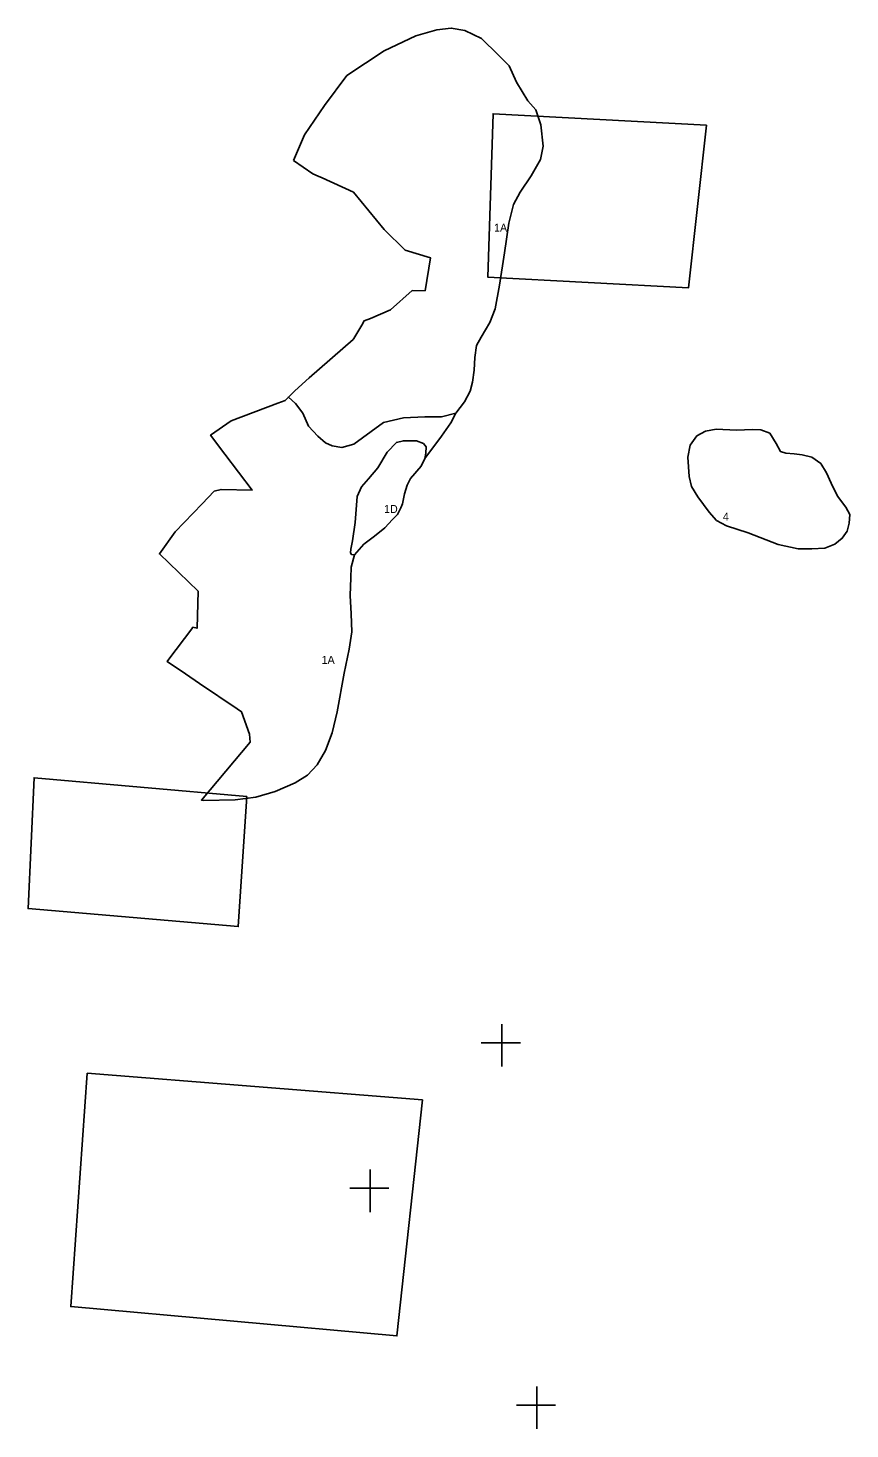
# Model space of a CAD drawing. Extents: x -439069 to -431150, y -1130245 to -1119273.
# Drawn here: x -439069 to -437837, y -1124070 to -1121968 of the extents above; entities that cross this region are included whole.
import ezdxf

# ---------------------------------------------------------------- set-up
doc = ezdxf.new("R2010")
doc.units = 0
for name, color, linetype in [('11510013_sesuvné území_Stav', 7, 'Continuous'), ('11540011_poddolované území_Stav', 7, 'Continuous'), ('svahové nestability přírodního charakteru dočasně uklidněné', 7, 'Continuous'), ('Svahové nestability přírodního charakteru uklidněné', 7, 'Continuous')]:
    doc.layers.add(name, color=color, linetype=linetype)

msp = doc.modelspace()

# ---------------------------------------------------------------- linework, layer by layer
at = {"layer": '11510013_sesuvné území_Stav'}
for p, q in [((-438358.9, -1123462.4), (-438358.9, -1123526.2)), ((-438389.6, -1123490.3), (-438331.1, -1123490.3)), ((-438556.1, -1123680.6), (-438556.1, -1123744.4)), ((-438586.7, -1123708.6), (-438528.2, -1123708.6)), ((-438306.5, -1124005.8), (-438306.5, -1124069.6)), ((-438337.1, -1124033.7), (-438278.6, -1124033.7))]:
    msp.add_line(p, q, dxfattribs=at)
at = {"layer": '11540011_poddolované území_Stav'}
for points in [[(-438052, -1122114), (-438372, -1122097), (-438380, -1122342), (-438079, -1122358), (-438052, -1122114)], [(-438741, -1123121), (-439060, -1123093), (-439069, -1123289), (-438754, -1123316), (-438741, -1123121)], [(-438477.5, -1123575.9), (-438980.2, -1123536.2), (-439005, -1123886), (-438516, -1123930), (-438477.5, -1123575.9)]]:
    msp.add_lwpolyline(points, dxfattribs=at)
at = {"layer": 'svahové nestability přírodního charakteru dočasně uklidněné'}
for points in [[(-438007, -1122571.7), (-438037.4, -1122570), (-438053.4, -1122572.9), (-438066.8, -1122580.1), (-438076.5, -1122594.1), (-438079.8, -1122612.2), (-438077.9, -1122641), (-438074.6, -1122656.3), (-438064.9, -1122671.7), (-438048.3, -1122694.5), (-438036.9, -1122707.1), (-438022, -1122715), (-437989.7, -1122725.5), (-437944.9, -1122743.3), (-437914.5, -1122749.4), (-437894.2, -1122749.5), (-437874.9, -1122748.4), (-437859.7, -1122742.5), (-437848.5, -1122733.6), (-437841.3, -1122723.2), (-437838.1, -1122711), (-437837, -1122698), (-437843, -1122687.3), (-437855.6, -1122670.5), (-437865.4, -1122651.3), (-437872, -1122635.7), (-437880.7, -1122621.5), (-437894.3, -1122612.2), (-437908.7, -1122608.8), (-437920.6, -1122607.1), (-437933.3, -1122606.1), (-437941.4, -1122603.6), (-437947.6, -1122591.8), (-437957.3, -1122576.3), (-437970.5, -1122571.2), (-437983.2, -1122570.5), (-438007, -1122571.7)], [(-438584.2, -1122758), (-438579.5, -1122758.4), (-438565.5, -1122742.8), (-438549.5, -1122730.5), (-438534.2, -1122718.2), (-438522.8, -1122705.6), (-438515.1, -1122698.2), (-438510.3, -1122688.3), (-438507.5, -1122682.1), (-438504.7, -1122667.2), (-438500.5, -1122654), (-438495.7, -1122644.1), (-438479.9, -1122625.4), (-438474.2, -1122613.9), (-438472.8, -1122606.1), (-438472.1, -1122596.6), (-438476.4, -1122591.5), (-438486.5, -1122587.5), (-438506.4, -1122587.5), (-438516.9, -1122589.9), (-438530.8, -1122604.7), (-438544.6, -1122628.3), (-438558.6, -1122644.7), (-438569.1, -1122656.6), (-438575.8, -1122671.2), (-438578.9, -1122709.9), (-438582.6, -1122737.5), (-438585.2, -1122750), (-438585.6, -1122755.5), (-438584.2, -1122758)]]:
    msp.add_lwpolyline(points, dxfattribs=at)
at = {"layer": 'Svahové nestability přírodního charakteru uklidněné'}
for points in [[(-438670.9, -1122167.1), (-438642, -1122187.1), (-438634, -1122190.7), (-438628.1, -1122193.4), (-438581.4, -1122214.7), (-438535, -1122270.7), (-438503.7, -1122301.5), (-438466, -1122313.1), (-438474, -1122362.6), (-438493.1, -1122362.3), (-438525.6, -1122391.2), (-438555.8, -1122403.9), (-438565.2, -1122407.8), (-438568.9, -1122414.1), (-438580.6, -1122434.2), (-438581.5, -1122435.6), (-438647.7, -1122493.2), (-438669.1, -1122512.5), (-438678.7, -1122522), (-438668.2, -1122531.8), (-438657, -1122545.9), (-438648.4, -1122565.6), (-438634.6, -1122580.8), (-438623.1, -1122590.5), (-438612.9, -1122595.2), (-438598.5, -1122597.7), (-438580.9, -1122592.5), (-438554.7, -1122573.4), (-438536.1, -1122560.3), (-438506, -1122553), (-438474.1, -1122551.5), (-438449.5, -1122551.7), (-438427.9, -1122546.3), (-438414.6, -1122529.3), (-438406.3, -1122513.2), (-438402.6, -1122499.4), (-438400.3, -1122481.5), (-438399.3, -1122462.7), (-438397, -1122444.8), (-438389.9, -1122432.1), (-438376.7, -1122410.3), (-438368.9, -1122389.5), (-438362.3, -1122354), (-438354.7, -1122305.6), (-438348.1, -1122260.9), (-438341.3, -1122233.1), (-438331.4, -1122214.8), (-438314.9, -1122190), (-438300.8, -1122165.9), (-438296.9, -1122145.5), (-438300.5, -1122113.8), (-438307.9, -1122091), (-438319.9, -1122077.8), (-438336.8, -1122049.7), (-438347.9, -1122025.1), (-438364.2, -1122008.5), (-438389.1, -1121984.3), (-438414.2, -1121972.4), (-438434.6, -1121968.5), (-438456.3, -1121971.4), (-438487.6, -1121980.4), (-438535.3, -1122002.7), (-438591.1, -1122039.6), (-438624.5, -1122084.5), (-438654.8, -1122128.8), (-438670.9, -1122167.1)], [(-438678.7, -1122522), (-438683.8, -1122527), (-438694.4, -1122531.1), (-438764.6, -1122557.8), (-438795.3, -1122579.1), (-438773.9, -1122607.6), (-438733.1, -1122661.7), (-438779.6, -1122660.5), (-438789.8, -1122662.9), (-438808, -1122682), (-438848.4, -1122724.2), (-438872, -1122757.1), (-438814, -1122813.1), (-438815.7, -1122868.8), (-438821.9, -1122867.3), (-438823.6, -1122869.5), (-438858, -1122915.2), (-438860.5, -1122918.5), (-438833.1, -1122937.1), (-438812.2, -1122951.3), (-438755.6, -1122989.3), (-438748.8, -1122993.9), (-438737, -1123027.6), (-438736.2, -1123039.5), (-438809.2, -1123126.5), (-438805.8, -1123126.9), (-438758.6, -1123126.2), (-438727.5, -1123122.1), (-438698.6, -1123113.3), (-438668.5, -1123100.7), (-438649.9, -1123089), (-438635.5, -1123073.4), (-438623.2, -1123051.8), (-438613.2, -1123025.7), (-438605.9, -1122994.2), (-438595.2, -1122936), (-438587.9, -1122899.9), (-438583.7, -1122874.3), (-438584.7, -1122847.3), (-438586, -1122819.5), (-438585.2, -1122793.1), (-438584.9, -1122777.2), (-438579.5, -1122758.4), (-438584.2, -1122758), (-438585.6, -1122755.5), (-438585.2, -1122750), (-438582.6, -1122737.5), (-438578.9, -1122709.9), (-438575.8, -1122671.2), (-438569.1, -1122656.6), (-438558.6, -1122644.7), (-438544.6, -1122628.3), (-438530.8, -1122604.7), (-438516.9, -1122589.9), (-438506.4, -1122587.5), (-438486.5, -1122587.5), (-438476.4, -1122591.5), (-438472.1, -1122596.6), (-438472.8, -1122606.1), (-438474.2, -1122613.9), (-438449.1, -1122580.4), (-438435.2, -1122560.8), (-438427.9, -1122546.3), (-438449.5, -1122551.7), (-438474.1, -1122551.5), (-438506, -1122553), (-438536.1, -1122560.3), (-438554.7, -1122573.4), (-438580.9, -1122592.5), (-438598.5, -1122597.7), (-438612.9, -1122595.2), (-438623.1, -1122590.5), (-438634.6, -1122580.8), (-438648.4, -1122565.6), (-438657, -1122545.9), (-438668.2, -1122531.8), (-438678.7, -1122522)]]:
    msp.add_lwpolyline(points, dxfattribs=at)

# ---------------------------------------------------------------- texts
at = {"layer": 'svahové nestability přírodního charakteru dočasně uklidněné'}
for s, p in [('1D', (-438535.4, -1122695.8)), ('4', (-438027.5, -1122707.2))]:
    msp.add_text(s, height=12, dxfattribs=at).set_placement(p)
at = {"layer": 'Svahové nestability přírodního charakteru uklidněné'}
for p in [(-438370.5, -1122273.9), (-438629, -1122922.1)]:
    msp.add_text('1A', height=12, dxfattribs=at).set_placement(p)

doc.saveas('drawing.dxf')
